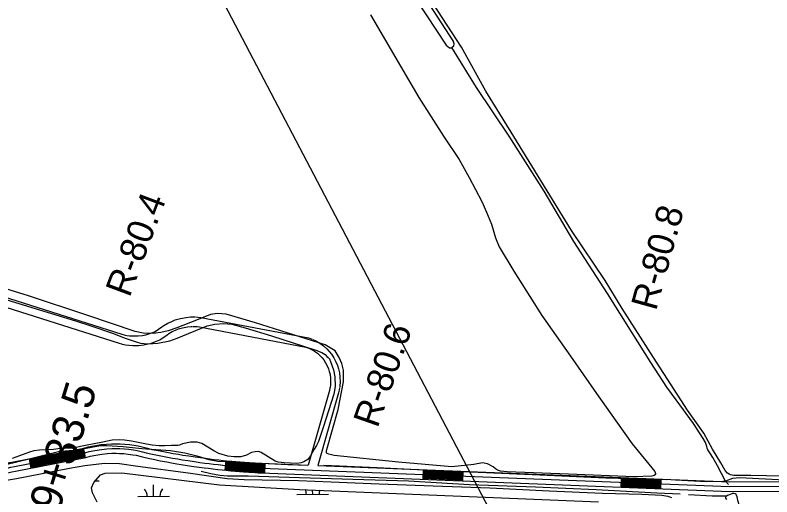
# Model space of a CAD drawing. Extents: x 3715084 to 3753216, y 488173 to 513963.
# Drawn here: x 3725790 to 3728178, y 502536 to 504056 of the extents above; entities that cross this region are included whole.
import ezdxf

# ---------------------------------------------------------------- set-up
doc = ezdxf.new("R2010")
doc.units = 0
for name, color, linetype in [('V-RIVR-RANG-IDEN', 7, 'Continuous'), ('V-ROAD-CNTR', 7, 'Continuous'), ('V-SITE-VEGE', 7, 'Continuous'), ('V-SURV-IDEN', 7, 'Continuous'), ('V-TOPO-BNDY', 7, 'Continuous'), ('V-TOPO-SHOR', 7, 'Continuous'), ('V-WETL-SWMP', 7, 'Continuous')]:
    doc.layers.add(name, color=color, linetype=linetype)

msp = doc.modelspace()

# ---------------------------------------------------------------- linework, layer by layer
at = {"layer": 'V-ROAD-CNTR'}
for p, q in [((3725929.5, 502674.6), (3725935.2, 502645.1)), ((3725956.7, 502679.9), (3725962.5, 502650.5)), ((3725834, 502655.9), (3725839.8, 502626.4)), ((3726454.4, 502650.1), (3726451.3, 502620.3)), ((3726578.1, 502641.2), (3726576.9, 502611.2)), ((3727077.7, 502621.4), (3727076.5, 502591.4)), ((3727202.6, 502616.4), (3727201.4, 502586.5)), ((3727702.2, 502596.7), (3727701, 502566.7)), ((3727827.1, 502591.7), (3727825.9, 502561.8))]:
    msp.add_line(p, q, dxfattribs=at)
for points in [[(3723510.9, 503350), (3725501, 502656.8), (3725509.7, 502654.2), (3725525.2, 502649.9), (3725539.1, 502646.6), (3725551.2, 502643.9), (3725566.9, 502640.9), (3725582.9, 502638.3), (3725598.3, 502636.3), (3725613.8, 502634.7), (3725624.8, 502633.8), (3725637.7, 502633.1), (3725652.6, 502632.6), (3725665, 502632.5), (3725680.5, 502632.8), (3725699.3, 502633.7), (3725713.7, 502634.9), (3725725.6, 502636.1), (3725739.8, 502637.9), (3725753.8, 502640.1), (3725761.9, 502641.5), (3725773.3, 502643.8), (3725784.8, 502646.2), (3726007.2, 502689.8)], [(3725148.7, 503359.4), (3726126.3, 503049.2), (3726134.4, 503047.1), (3726142.9, 503045.4), (3726150.4, 503044.4)], [(3723505.9, 503335.8), (3725496.4, 502642.5), (3725505.5, 502639.8), (3725521.5, 502635.4), (3725535.7, 502631.9), (3725548.1, 502629.2), (3725564.3, 502626.1), (3725580.7, 502623.5), (3725596.5, 502621.4), (3725612.4, 502619.7), (3725623.8, 502618.8), (3725637, 502618.1), (3725652.3, 502617.6), (3725665.1, 502617.5), (3725681, 502617.8), (3725700.3, 502618.8), (3725715.1, 502619.9), (3725727.4, 502621.2), (3725741.9, 502623.1), (3725756.2, 502625.3), (3725764.6, 502626.8), (3725776.4, 502629.1), (3725787.8, 502631.5), (3726010.1, 502675.1)], [(3725136.7, 503331.7), (3726118, 503020.3), (3726125.6, 503018.4)], [(3723501, 503321.6), (3725491.8, 502628.2), (3725501.4, 502625.4), (3725517.7, 502620.9), (3725532.3, 502617.3), (3725545.1, 502614.5), (3725561.7, 502611.3), (3725578.5, 502608.6), (3725594.8, 502606.5), (3725611, 502604.8), (3725622.8, 502603.9), (3725636.3, 502603.1), (3725652, 502602.6), (3725665.2, 502602.5), (3725681.6, 502602.8), (3725701.2, 502603.8), (3725716.5, 502605), (3725729.1, 502606.3), (3725744, 502608.2), (3725758.7, 502610.5), (3725767.3, 502612), (3725779.4, 502614.4), (3725790.9, 502616.9), (3726012.9, 502660.4)], [(3726150.4, 503044.4), (3726151.6, 503044.2), (3726162.5, 503043.4), (3726170.5, 503043.4), (3726177.9, 503043.7), (3726191.4, 503045.3), (3726202.5, 503047.5), (3726208.3, 503049), (3726217.9, 503052.1), (3726224.5, 503054.7), (3726232, 503058), (3726253, 503072), (3726259.4, 503076.3), (3726272, 503083.7), (3726284.3, 503089.5), (3726295.4, 503093.9), (3726311.4, 503098.6), (3726330.1, 503102.1), (3726343.6, 503103.4), (3726354.4, 503103.6), (3726357.8, 503103.5)], [(3726360.1, 503103.4), (3726366.7, 503103.1), (3726376.2, 503102), (3726715.2, 503037.6), (3726727.6, 503033)], [(3726125.6, 503018.4), (3726127.7, 503017.8), (3726138, 503015.8), (3726148.5, 503014.3), (3726161.3, 503013.4), (3726171, 503013.4), (3726180.3, 503013.8), (3726196.1, 503015.6), (3726209.3, 503018.3), (3726216.7, 503020.2), (3726227.9, 503023.8), (3726236.1, 503027), (3726246.6, 503031.7), (3726269.7, 503047.1), (3726275.3, 503050.9), (3726286, 503057.1), (3726296.2, 503062), (3726305.2, 503065.5), (3726318.4, 503069.4), (3726334.2, 503072.4), (3726345.3, 503073.4), (3726349.9, 503073.5)], [(3726351.9, 503073.6), (3726354.1, 503073.6), (3726364.4, 503073.1), (3726371.8, 503072.3), (3726707.1, 503008.6), (3726717.1, 503004.9), (3726720.6, 503003.2)], [(3726729.1, 503032.4), (3726741, 503026.7), (3726750.9, 503020.8), (3726762.5, 503012.4), (3726773.4, 503002.6), (3726781.1, 502994.3), (3726787.9, 502985.6), (3726795.3, 502974.5), (3726801.8, 502962.3), (3726806.8, 502950.3), (3726810.2, 502939.7), (3726813.1, 502927.5), (3726815, 502913.3), (3726815.4, 502898.4), (3726814.5, 502884.9), (3726814.1, 502882.5)], [(3726720.6, 503003.2), (3726726.7, 503000.2), (3726734.3, 502995.7), (3726743.6, 502989), (3726752.3, 502981.1), (3726758.3, 502974.7), (3726763.6, 502968), (3726769.5, 502959.2), (3726774.7, 502949.4), (3726778.7, 502939.9), (3726781.3, 502931.7), (3726783.5, 502922.1), (3726785, 502910.8), (3726785.4, 502899), (3726784.7, 502888.3), (3726783.7, 502882.2)], [(3726783.7, 502882.2), (3726783.1, 502878.7), (3726781.4, 502871.7), (3726714.1, 502635.8)], [(3726813.8, 502880.6), (3726812.6, 502872.9), (3726810.5, 502864.1), (3726745, 502634.6)], [(3725785, 502646.3), (3726006.7, 502689.7), (3726020.4, 502693.3), (3726038.8, 502697.2), (3726060.3, 502700.5), (3726078.7, 502702.3), (3726094.2, 502703.2), (3726109, 502703.4), (3726121, 502703.1), (3726135.9, 502702.2), (3726150.4, 502700.7), (3726166.1, 502698.5), (3726178, 502696.4), (3726195, 502692.6), (3726207.7, 502689.2), (3726221.7, 502685.7), (3726236.5, 502682.7), (3726253, 502679.5), (3726273.6, 502675.6), (3726289, 502672.9), (3726305.3, 502670.1), (3726319.1, 502667.8), (3726337.6, 502664.9), (3726358.3, 502661.8), (3726374.5, 502659.6), (3726390.3, 502657.5), (3726403.9, 502655.7), (3726417.8, 502654.1), (3726432.5, 502652.4), (3726446.8, 502650.9), (3726457.3, 502649.8), (3726473.7, 502648.3), (3726486.8, 502647.1), (3726500.5, 502645.9), (3726513.2, 502645), (3726529.1, 502643.8), (3726548.1, 502642.6), (3726558.6, 502642), (3726567.7, 502641.6), (3726714.1, 502635.8)], [(3725787.8, 502631.5), (3726010.1, 502675.1), (3726023.9, 502678.7), (3726041.5, 502682.4), (3726062.2, 502685.6), (3726079.8, 502687.4), (3726094.7, 502688.2), (3726108.9, 502688.4), (3726120.4, 502688.1), (3726134.7, 502687.2), (3726148.6, 502685.8), (3726163.7, 502683.7), (3726175, 502681.7), (3726191.5, 502678), (3726204, 502674.7), (3726218.4, 502671.1), (3726233.6, 502668), (3726250.1, 502664.8), (3726270.9, 502660.9), (3726286.4, 502658.1), (3726302.9, 502655.3), (3726316.7, 502653), (3726335.4, 502650.1), (3726356.2, 502647), (3726372.5, 502644.7), (3726388.4, 502642.6), (3726402.1, 502640.9), (3726416, 502639.2), (3726430.9, 502637.5), (3726445.3, 502636), (3726455.9, 502634.9), (3726472.3, 502633.3), (3726485.6, 502632.1), (3726499.3, 502631), (3726512.1, 502630), (3726528.1, 502628.9), (3726547.2, 502627.7), (3726557.8, 502627.1), (3726567, 502626.6), (3728044.9, 502568.1), (3728491.2, 502569.3)], [(3725930, 502671.6), (3726007.7, 502686.9)], [(3725930.6, 502668.7), (3726008.3, 502683.9)], [(3725790.7, 502616.8), (3726013.4, 502660.5), (3726027.3, 502664.1), (3726044.2, 502667.7), (3726064.1, 502670.7), (3726081, 502672.4), (3726095.2, 502673.2), (3726108.8, 502673.4), (3726119.8, 502673.1), (3726133.5, 502672.3), (3726146.8, 502671), (3726161.4, 502668.9), (3726172.1, 502667), (3726187.9, 502663.4), (3726200.2, 502660.2), (3726215, 502656.5), (3726230.6, 502653.3), (3726247.3, 502650), (3726268.2, 502646.1), (3726283.8, 502643.3), (3726300.4, 502640.5), (3726314.3, 502638.2), (3726333.1, 502635.2), (3726354, 502632.1), (3726370.4, 502629.8), (3726386.5, 502627.7), (3726400.2, 502626), (3726414.3, 502624.3), (3726429.2, 502622.6), (3726443.7, 502621), (3726454.4, 502620), (3726470.9, 502618.4), (3726484.3, 502617.2), (3726498.1, 502616), (3726511, 502615), (3726527.1, 502613.9), (3726546.3, 502612.7), (3726557, 502612.1), (3726566.3, 502611.6), (3728044.6, 502553.1), (3728491.1, 502554.3)], [(3725834.6, 502652.9), (3725957.3, 502677)], [(3725835.2, 502650), (3725957.8, 502674)], [(3725835.7, 502647), (3725958.4, 502671.1)], [(3725836.3, 502644.1), (3725959, 502668.1)], [(3725836.9, 502641.2), (3725959.6, 502665.2)], [(3725837.5, 502638.2), (3725960.1, 502662.2)], [(3725838.1, 502635.3), (3725960.7, 502659.3)], [(3725931.2, 502665.7), (3726008.9, 502681)], [(3725931.8, 502662.8), (3726009.5, 502678)], [(3725932.3, 502659.9), (3726010.1, 502675.1)], [(3725932.9, 502656.9), (3726010.6, 502672.1)], [(3725933.5, 502654), (3726011.2, 502669.2)], [(3725934.1, 502651), (3726011.8, 502666.3)], [(3725934.7, 502648.1), (3726012.4, 502663.3)], [(3725838.6, 502632.3), (3725961.3, 502656.4)], [(3725839.2, 502629.4), (3725961.9, 502653.4)], [(3726452.9, 502635.2), (3726455.9, 502634.9), (3726472.3, 502633.3), (3726485.6, 502632.1), (3726499.3, 502631), (3726512.1, 502630), (3726528.1, 502628.9), (3726547.2, 502627.7), (3726557.8, 502627.1), (3726567, 502626.6), (3726577.5, 502626.2)], [(3726453.2, 502638.2), (3726456.2, 502637.9), (3726472.6, 502636.3), (3726485.8, 502635.1), (3726499.6, 502634), (3726512.4, 502633), (3726528.3, 502631.9), (3726547.4, 502630.7), (3726558, 502630.1), (3726567.2, 502629.6), (3726577.6, 502629.2)], [(3726453.5, 502641.2), (3726456.4, 502640.9), (3726472.8, 502639.3), (3726486.1, 502638.1), (3726499.8, 502637), (3726512.6, 502636), (3726528.5, 502634.9), (3726547.6, 502633.7), (3726558.2, 502633.1), (3726567.3, 502632.6), (3726577.7, 502632.2)], [(3726453.8, 502644.1), (3726456.7, 502643.8), (3726473.1, 502642.3), (3726486.3, 502641.1), (3726500, 502640), (3726512.8, 502639), (3726528.7, 502637.9), (3726547.8, 502636.7), (3726558.3, 502636.1), (3726567.5, 502635.6), (3726577.9, 502635.2)], [(3726454.1, 502647.1), (3726457, 502646.8), (3726473.4, 502645.3), (3726486.6, 502644.1), (3726500.3, 502643), (3726513, 502642), (3726528.9, 502640.8), (3726547.9, 502639.6), (3726558.5, 502639.1), (3726567.6, 502638.6), (3726578, 502638.2)], [(3726745, 502634.6), (3728045.2, 502583.1), (3728491.3, 502584.3)], [(3726451.6, 502623.2), (3726454.7, 502622.9), (3726471.2, 502621.4), (3726484.5, 502620.2), (3726498.4, 502619), (3726511.3, 502618), (3726527.3, 502616.9), (3726546.5, 502615.7), (3726557.2, 502615.1), (3726566.5, 502614.6), (3726577, 502614.2)], [(3726451.9, 502626.2), (3726455, 502625.9), (3726471.5, 502624.4), (3726484.8, 502623.2), (3726498.6, 502622), (3726511.5, 502621), (3726527.5, 502619.9), (3726546.7, 502618.7), (3726557.3, 502618.1), (3726566.6, 502617.6), (3726577.2, 502617.2)], [(3726452.2, 502629.2), (3726455.3, 502628.9), (3726471.7, 502627.3), (3726485, 502626.2), (3726498.9, 502625), (3726511.7, 502624), (3726527.7, 502622.9), (3726546.9, 502621.7), (3726557.5, 502621.1), (3726566.8, 502620.6), (3726577.3, 502620.2)], [(3726452.6, 502632.2), (3726455.6, 502631.9), (3726472, 502630.3), (3726485.3, 502629.1), (3726499.1, 502628), (3726511.9, 502627), (3726527.9, 502625.9), (3726547.1, 502624.7), (3726557.7, 502624.1), (3726566.9, 502623.6), (3726577.4, 502623.2)], [(3727077.4, 502612.4), (3727202.3, 502607.5)], [(3727077.5, 502615.4), (3727202.4, 502610.5)], [(3727077.6, 502618.4), (3727202.5, 502613.5)], [(3727076.6, 502594.4), (3727201.5, 502589.5)], [(3727076.8, 502597.4), (3727201.7, 502592.5)], [(3727076.9, 502600.4), (3727201.8, 502595.5)], [(3727077, 502603.4), (3727201.9, 502598.5)], [(3727077.1, 502606.4), (3727202, 502601.5)], [(3727077.2, 502609.4), (3727202.1, 502604.5)], [(3727701.9, 502587.7), (3727826.8, 502582.7)], [(3727702, 502590.7), (3727826.9, 502585.7)], [(3727702.1, 502593.7), (3727827, 502588.7)], [(3727701.2, 502569.7), (3727826.1, 502564.8)], [(3727701.3, 502572.7), (3727826.2, 502567.8)], [(3727701.4, 502575.7), (3727826.3, 502570.8)], [(3727701.5, 502578.7), (3727826.4, 502573.8)], [(3727701.6, 502581.7), (3727826.5, 502576.7)], [(3727701.7, 502584.7), (3727826.6, 502579.7)]]:
    msp.add_lwpolyline(points, dxfattribs=at)
at = {"layer": 'V-SITE-VEGE'}
for points in [[(3728209.6, 502600.8), (3728111.1, 502602.8), (3728057.6, 502603.6), (3728047.5, 502605.7), (3728042.4, 502607), (3728037.1, 502611), (3728030.4, 502619.4), (3728016.5, 502642.9), (3727989.8, 502686.3), (3727962.7, 502737.1), (3727911.7, 502809.7), (3727803.6, 502976), (3727705.5, 503129.8), (3727651.7, 503218.3), (3727545.7, 503376), (3727448.4, 503534), (3727355.2, 503686), (3727275.1, 503815.5), (3727197.9, 503954.8), (3727152.6, 504024.5), (3727066.6, 504157.3)], [(3726911, 504056.8), (3727006.1, 503894.5), (3727063.7, 503795.7), (3727141.8, 503673.5), (3727191.2, 503600.7), (3727223, 503543.8), (3727262.6, 503467.7), (3727277.1, 503434.1), (3727293.2, 503395.9), (3727305.1, 503353.4), (3727317.6, 503324.2), (3727363.7, 503247.9), (3727451.5, 503107.7), (3727541.8, 502979.2), (3727624.6, 502862.4), (3727685.6, 502775.3), (3727736.8, 502702.9), (3727808.1, 502615.5), (3727810.7, 502609.4), (3727809.9, 502606.7), (3727806.4, 502603.1), (3727799.3, 502600.7), (3727743.1, 502599.4), (3727535.5, 502607.1), (3727342.6, 502615), (3727321.7, 502617.1), (3727312.1, 502620.2), (3727306, 502624.1), (3727298.7, 502631), (3727280.6, 502640.3), (3727264.2, 502643.2)], [(3727264.2, 502643.2), (3727237.1, 502638.4), (3727168.2, 502630.3), (3726999.2, 502645.4), (3726796.3, 502666.5), (3726779.6, 502670.2), (3726774.3, 502672.3), (3726772.5, 502674.7), (3726771.9, 502679.6), (3726773.6, 502685.3), (3726809.5, 502811.4), (3726826.5, 502899.2), (3726826, 502935.4), (3726821.2, 502956.6), (3726812.9, 502975.9), (3726799.4, 502996.3), (3726767.9, 503015.8), (3726548.5, 503085), (3726456, 503112.2), (3726428.5, 503114.1), (3726406.5, 503111.3), (3726362.5, 503093.8), (3726300.4, 503068.8), (3726273.3, 503059.6), (3726249.3, 503054.4), (3726225.8, 503051.6), (3726194.3, 503052.3), (3726168.3, 503057.3), (3726015.9, 503109), (3725832, 503170.5), (3725569.3, 503251)], [(3723736, 503215.8), (3724265.5, 503029.4), (3724509.6, 502942.6), (3724759.3, 502860.4), (3724998.8, 502773.2), (3725254.7, 502680.4), (3725487.2, 502599.4), (3725526.9, 502588.9), (3725548.8, 502584.2), (3725598.6, 502577.1), (3725633.4, 502573.3), (3725692.7, 502577.3), (3725737.7, 502583.9), (3725794.1, 502594)], [(3725763.9, 503157.9), (3725980.7, 503091.3), (3726029, 503075.5), (3726097.3, 503052.4), (3726137.6, 503036.4), (3726172.1, 503024.5), (3726186, 503021.2), (3726209, 503019), (3726240.7, 503020.4), (3726278.6, 503027.7), (3726301, 503036.4), (3726396.2, 503075.7), (3726420.3, 503080.9), (3726448.8, 503083.3), (3726474, 503080.3), (3726515.9, 503069.6), (3726598.8, 503043.8), (3726738.7, 502999.1), (3726757.8, 502990.9), (3726768.3, 502984.6), (3726773.8, 502979.1), (3726777.9, 502975.2), (3726781.5, 502971.3), (3726785.2, 502963.2), (3726794.8, 502936.7), (3726799, 502914), (3726799.3, 502884.1), (3726795.3, 502859.3), (3726762.2, 502754.4), (3726747, 502710.7), (3726740.4, 502698.1), (3726733.6, 502686.3), (3726722.2, 502665.6), (3726713.4, 502653.2), (3726701.3, 502645.8), (3726692.6, 502643.1), (3726678.5, 502641.1), (3726638.6, 502643.1), (3726619.7, 502645.6), (3726610.8, 502647.9), (3726588.4, 502662), (3726565.9, 502675.8), (3726558.2, 502679.3), (3726547, 502678.1), (3726536.2, 502675.3), (3726519.6, 502667), (3726502.3, 502662.2), (3726481.2, 502661.6), (3726461, 502664.2), (3726432.6, 502672.8), (3726416.5, 502680.6), (3726379.1, 502703.7), (3726363.9, 502708.1), (3726342.9, 502708), (3726317.7, 502702.8), (3726308.9, 502699), (3726303.1, 502698.1), (3726283.1, 502698), (3726261.9, 502697.3), (3726244.3, 502697.3), (3726222.5, 502698.4), (3726204.8, 502701.8), (3726157.1, 502711.1), (3726134.7, 502714.5), (3726120.6, 502715.7), (3726095.9, 502714.4), (3726067, 502708.4), (3726039.4, 502703.6), (3726017, 502699.4), (3725996.4, 502695.2), (3725973.5, 502689.2), (3725955.8, 502689.2), (3725939.3, 502689.1), (3725911.3, 502685.6), (3725867.4, 502682.9), (3725849.5, 502680.7), (3725835.4, 502676.5), (3725803.8, 502665.4), (3725781.2, 502656.9)], [(3725794.1, 502594), (3725961.2, 502626.5), (3726010.3, 502634.5), (3726072.1, 502641.8), (3726119.7, 502640.8), (3726177.2, 502632.4), (3726336.2, 502611.3), (3726459, 502593.3), (3726512.9, 502590.3), (3726684.1, 502587.4), (3726787.6, 502583.7), (3726938.7, 502577.1), (3727108.5, 502570.7), (3727287.7, 502564.2), (3727475, 502554.5), (3727643.2, 502547.6), (3727766.9, 502544.5), (3727830.4, 502541), (3727849.1, 502538.1), (3727861.4, 502534.3)]]:
    msp.add_lwpolyline(points, dxfattribs=at)
at = {"layer": 'V-TOPO-BNDY'}
msp.add_line((3723872.6, 509005.3), (3727628.3, 501843.7), dxfattribs=at)
at = {"layer": 'V-TOPO-SHOR'}
msp.add_line((3727245.3, 503826.9), (3727167.6, 503954), dxfattribs=at)
for points in [[(3725959.7, 505873), (3725974.5, 505854.6), (3726022.9, 505776.6), (3726085.6, 505684.1), (3726109.7, 505652.3), (3726170.8, 505543.9), (3726217.2, 505466.5), (3726352.8, 505242.1), (3726513.7, 504998.6), (3726630.1, 504813), (3726769.5, 504601.5), (3726814.8, 504523.5), (3726949.4, 504317.8), (3727172.7, 503971)], [(3726793.4, 504507.5), (3726930.5, 504295.3), (3727149.6, 503960.7), (3727160.6, 503952.1), (3727165.3, 503952.9), (3727167.6, 503954), (3727170.4, 503955.3), (3727174.4, 503959.2), (3727174.7, 503965.1), (3727172.7, 503971)], [(3728040.8, 502574.5), (3728031.6, 502585.3), (3728006.1, 502633.7), (3727990.8, 502659.9), (3727983.7, 502671.2), (3727979.3, 502677.4), (3727975.4, 502683.9), (3727973, 502689.7), (3727972, 502695.2), (3727970.2, 502701.4), (3727968.2, 502707.4), (3727961.2, 502719.7), (3727930.6, 502766.8), (3727875.8, 502841.5), (3727846.4, 502882.1), (3727796.1, 502959.3), (3727737.1, 503053.1), (3727659, 503177.3), (3727553.1, 503341.6), (3727459, 503500), (3727348.9, 503673.8), (3727245.3, 503826.9)], [(3725935.2, 502679.9), (3725838.4, 502655.7), (3725761.2, 502637.3), (3725716.2, 502629.7), (3725692.2, 502627.9), (3725660.5, 502627.8), (3725595.7, 502634.6), (3725499.8, 502656.8), (3725393.9, 502690.9), (3725290.1, 502730.9), (3725184.5, 502769), (3725113.6, 502792.2), (3724985.6, 502836.6), (3724838.7, 502888.7), (3724679.7, 502944.1), (3724557.2, 502985.9), (3724424.2, 503033.4), (3724258.9, 503090), (3724139, 503134.5), (3724040.6, 503169.7), (3723963.4, 503193.6), (3723923, 503208)], [(3725935.2, 502679.9), (3725985.6, 502683.9), (3726059, 502697.8), (3726078.5, 502698), (3726130.8, 502695.1), (3726189.9, 502688), (3726280.5, 502682.6)], [(3726280.5, 502682.6), (3726325.6, 502674.9), (3726363.8, 502664.8), (3726401, 502653.8), (3726429.7, 502648.5), (3726506.2, 502644.9), (3726650.4, 502637.9), (3726713.3, 502635.4)], [(3726764, 502636.3), (3726813.7, 502633.7), (3726932.6, 502628.5), (3727122.3, 502619.3), (3727275.7, 502612.7), (3727445, 502605.3), (3727654, 502596), (3727814.7, 502591.2), (3727846.5, 502590.2)], [(3726377.2, 502617), (3726407.1, 502609.9), (3726435.5, 502604.3), (3726459.7, 502601.8), (3726525.8, 502602), (3726687.4, 502597.3), (3726855.2, 502591.4), (3727030.7, 502586.2), (3727223.8, 502575.1), (3727432.2, 502567.9), (3727623.6, 502559.4), (3727814.1, 502548.9), (3727888, 502545.1)], [(3728573, 502625.9), (3728405.9, 502594.4), (3728382.4, 502588.4), (3728364, 502583.8), (3728338.4, 502583.1), (3728217.3, 502588.8), (3728076.6, 502596), (3728053.3, 502593.5), (3728031.6, 502585.3)], [(3727873.7, 502589.1), (3727971.3, 502584.3), (3728023.2, 502585.4), (3728031.6, 502585.3)], [(3727914.3, 502542.9), (3727989.3, 502539.3), (3728034.1, 502538.8)], [(3728035.5, 502527.6), (3728032.7, 502532), (3728032.1, 502534.9), (3728034.1, 502538.8), (3728037.4, 502541), (3728042, 502542.4), (3728047.3, 502544.8), (3728051.8, 502546.6), (3728054.6, 502547.2), (3728057.5, 502547.2), (3728061.8, 502546.6), (3728064, 502545.3)], [(3728245.3, 502286.8), (3728163.3, 502424.5), (3728129.5, 502468.7), (3728119.4, 502480.9), (3728101, 502497.2), (3728089.6, 502504), (3728081.9, 502507.1), (3728076.7, 502509.9), (3728075, 502511.2), (3728073.8, 502513.6), (3728071.8, 502518.3), (3728070.6, 502524), (3728069.6, 502530.5), (3728068.4, 502535.6), (3728066, 502541.1), (3728064, 502545.3)]]:
    msp.add_lwpolyline(points, dxfattribs=at)
at = {"layer": 'V-WETL-SWMP'}
for p, q in [((3726042.6, 502585.9), (3726055, 502586.1)), ((3726226.9, 502537.5), (3726226.5, 502573.5)), ((3726177, 502536.8), (3726276.9, 502538.1)), ((3726678.8, 502543.1), (3726778.8, 502544.4)), ((3726728.8, 502543.7), (3726728.6, 502557.7))]:
    msp.add_line(p, q, dxfattribs=at)
msp.add_lwpolyline([(3726048.4, 502519.3), (3726034.2, 502548.4), (3726031, 502564.1), (3726038.8, 502581.4), (3726059.1, 502605.1), (3726074.1, 502610.7), (3726126.8, 502611.7), (3726435.3, 502573.4), (3726687, 502559.4), (3727630.4, 502519.6)], dxfattribs=at)
for centre, start, end in [((3726171.7, 502537.2), 359.9442, 41.4878), ((3726282.2, 502538.6), 139.9442, 181.4878), ((3726673.6, 502543.5), 359.9442, 25.3964), ((3726784.1, 502544.9), 160.4113, 181.4878)]:
    msp.add_arc(centre, 35.2, start, end, dxfattribs=at)

# ---------------------------------------------------------------- texts
at = {"layer": 'V-RIVR-RANG-IDEN'}
for s, rotation, p in [('R-80.4', 69.5161, (3726150.8, 503162.4)), ('R-80.8', 74.5275, (3727812, 503120.3)), ('R-80.6', 70.7421, (3726933.2, 502750.4))]:
    msp.add_text(s, height=83, rotation=rotation, dxfattribs=at).set_placement(p)
at = {"layer": 'V-SURV-IDEN'}
msp.add_text('29+33.5', height=100, rotation=72.9067, dxfattribs=at).set_placement((3725906.3, 502412.9))

doc.saveas('drawing.dxf')
